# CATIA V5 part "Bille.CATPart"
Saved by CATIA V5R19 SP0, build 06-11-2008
Part number: Bille
Bounding box of the stored display mesh (mm): x -8.66 to 8.66, y -9.942 to 9.942, z -9.942 to 9.942
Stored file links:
  E:\IAO_2010\iao\IAO_MMS_Groupe2\IAO_MMS_Groupe2\svallart\Assemblage\Bille.CATPart
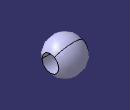
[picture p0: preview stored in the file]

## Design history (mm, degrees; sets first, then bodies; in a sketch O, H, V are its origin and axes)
Body1 (main body)
  Sketch1 on zx-plane, origin (0, 0, 0), H (-1, 0, 0), V (0, 0, 1)
    arc A1 centre (0, 0) radius 10 from (10, 0) to (-10, 0) ccw
    point P1 (-10, 0)
    point P2 (10, 0)
    distance P1 P2 = 20
    coincidence: P1 H, P2 H
  Shaft1: profile Sketch1, axis Sketch1.H, angle 360
  Plane1: type Offset, RefPlane yz-plane, Offset 10
  Sketch2 on Plane1, origin (10, 0, 0), H (0, 1, 0), V (0, 0, 1)
    circle A1 centre (0, 0) radius 5
    radius A1 = 5
  Pocket1: profile Sketch2, direction (-1, 0, 0), through (limit type 3)
  Sketch3 on yz-plane, origin (0, 0, 0), H (0, 1, 0), V (0, 0, 1)
    circle A1 centre (0, 0) radius 10
  Sketch4 on zx-plane, origin (0, 0, 0), H (-1, 0, 0), V (0, 0, 1)
    axis line L1 (-10, 0) -> (10, 0)
    horizontal: L1 H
